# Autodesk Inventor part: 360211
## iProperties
Shininess: 64.0
Angle Display Precision: 2
Document Length Units: 11269
Document Angle Units: 11279
Document Time Units: 11290
Document Mass Units: 11283
Document Length Units Precision: 3
Document Angle Units Precision: 2
Compacted: True
Created: 2006-01
Part Number: 360211
Document SubType Name: Modeling
Designer: I.Baliuc
Material: 1.1200
Description: Druckfeder
Vendor: Guterkunst
Density: 7.84 g/cm^3
Density: 0.0
Volumn: 0.0
Area: 0.0
PropertySet Name: Model Information
Control State: 0
Master: False
Checked Out: False
HalbzeugNorm: D-263M-04
Zweck: für Hauptkontakt
Abmessung: 2.2x19.0x18.5
Author: T.Messerschmitt
Revision Number: 360211
Comments: d = 2,2 mm; Dm = 16,8 mm; Da = 19 mm; if = 14,5; C = 3,47 N/mm; Ln = 42,7 mm; Lo = 98 mm; S = 52,3 mm; Fn = 181 N;
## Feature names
1. Coil1
2. Extrusion1
3. Extrusion3
4. Extrusion2
